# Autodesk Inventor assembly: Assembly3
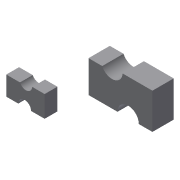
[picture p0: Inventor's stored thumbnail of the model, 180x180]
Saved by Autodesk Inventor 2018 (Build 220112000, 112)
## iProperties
Created: 2017-06
Part Number: Assembly3
Document SubType Name: Assembly
Designer: CADCIM 00
Author: CADCIM 00
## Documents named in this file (4)
- E:\_Deepak\Inventor\Autodesk Inventor_2017_Project\Resources\Inventor_2018_tut\c18_Inv_tut_2018\c18_tut04_inv\Assembly3.iam
- E:\_Deepak\Inventor\Autodesk Inventor_2017_Project\Resources\Inventor_2018_tut\c18_Inv_tut_2018\c18_tut04_inv\c18_tut04_inv-01.ipt
- E:\_Deepak\Inventor\Autodesk Inventor_2017_Project\Resources\Inventor_2018_tut\c18_Inv_tut_2018\c18_tut04_inv\c18_tut04_inv.ipt
- E:\_Deepak\Inventor\Autodesk Inventor_2017_Project\Resources\Inventor_2018_tut\c18_Inv_tut_2018\c18_tut04_inv\c18_tut04_inv-011.ipt
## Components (2 placed, 2 different names)
1. c18_tut04_inv-01:1
2. c18_tut04_inv-011:2
